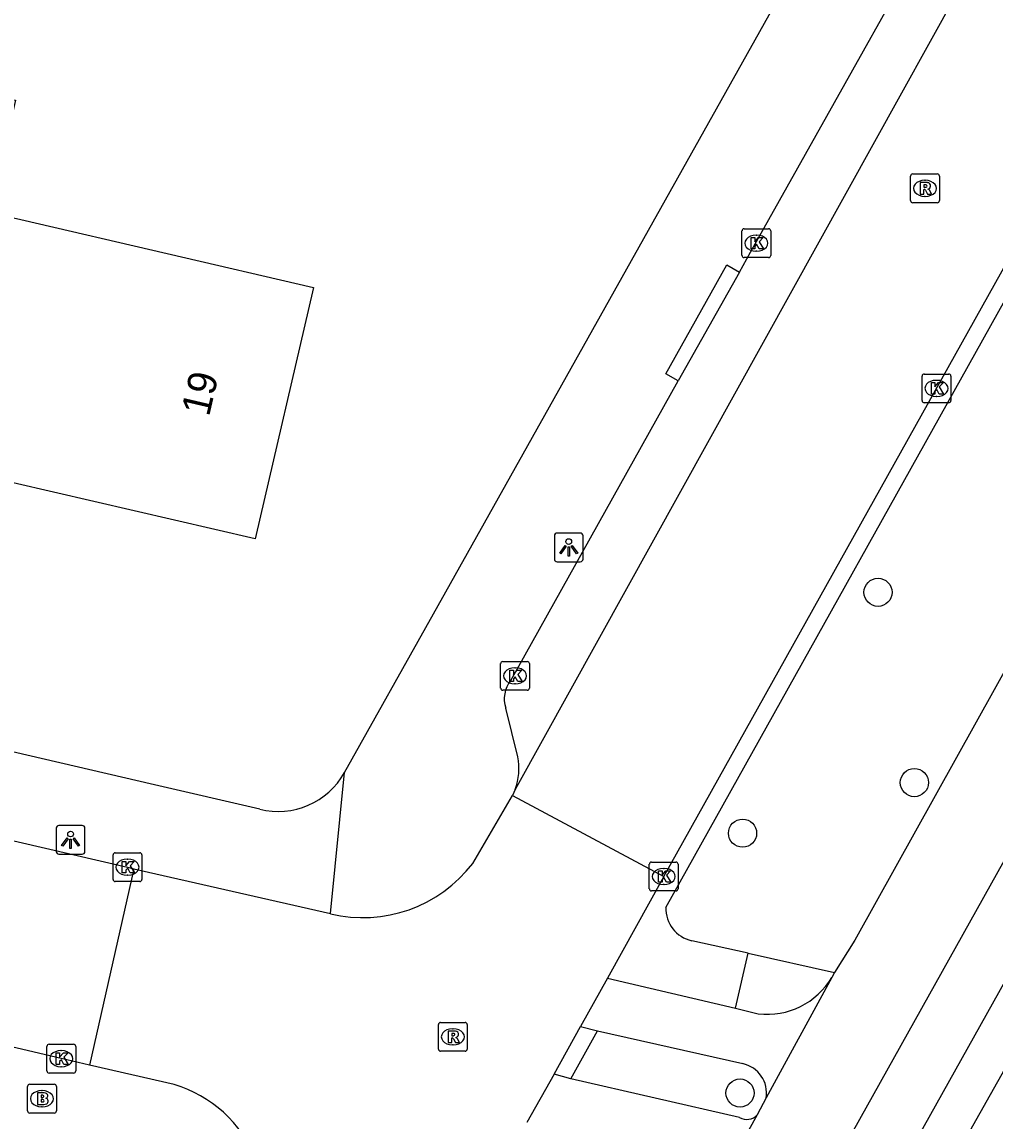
# Model space of a CAD drawing. Extents: x 162186 to 163152, y 385513 to 386513.
# Drawn here: x 162742.5 to 162776.34, y 385892.33 to 385930.55 of the extents above; entities that cross this region are included whole.
import ezdxf

# ---------------------------------------------------------------- set-up
doc = ezdxf.new("R2010")
doc.units = 0
for name, color, linetype in [('IMGEO_Boom', 7, 'Continuous'), ('IMGEO_Brandkraan', 7, 'Continuous'), ('IMGEO_Fietspad_gesloten', 7, 'Continuous'), ('IMGEO_Fietspad_open', 7, 'Continuous'), ('IMGEO_Groenvoorziening', 7, 'Continuous'), ('IMGEO_Kolk', 7, 'Continuous'), ('IMGEO_Lichtpunt', 7, 'Continuous'), ('IMGEO_Pand', 7, 'Continuous'), ('IMGEO_Pand_nummerreeks', 7, 'Continuous'), ('IMGEO_Rijbaan_lokaal_gesloten', 7, 'Continuous'), ('IMGEO_Rijbaan_lokaal_open', 7, 'Continuous'), ('IMGEO_Rioolput', 7, 'Continuous'), ('IMGEO_Voetpad_open', 7, 'Continuous')]:
    doc.layers.add(name, color=color, linetype=linetype)

msp = doc.modelspace()

# ---------------------------------------------------------------- linework, layer by layer
at = {"layer": 'IMGEO_Boom'}
for centre in [(162772.272, 385910.719), (162773.537, 385904.102), (162767.563, 385902.343), (162767.474, 385893.308)]:
    msp.add_circle(centre, 0.489, dxfattribs=at)
at = {"layer": 'IMGEO_Brandkraan'}
for p, q in [((162742.699, 385892.685), (162742.699, 385893.537)), ((162742.774, 385893.611), (162743.626, 385893.611)), ((162743.7, 385893.537), (162743.7, 385892.685)), ((162743.187, 385893.391), (162743.212, 385893.391)), ((162743.21, 385892.831), (162743.185, 385892.831)), ((162743.626, 385892.611), (162742.774, 385892.611))]:
    msp.add_line(p, q, dxfattribs=at)
for points in [[(162742.699, 385892.685), (162742.699, 385893.537)], [(162742.774, 385893.611), (162743.626, 385893.611)], [(162743.7, 385893.537), (162743.7, 385892.685)], [(162743.047, 385893.311), (162743.047, 385892.911), (162743.26, 385892.911)], [(162743.278, 385893.311), (162743.047, 385893.311)], [(162743.226, 385893.23), (162743.172, 385893.23), (162743.172, 385893.154)], [(162743.172, 385893.154), (162743.225, 385893.154)], [(162743.234, 385893.078), (162743.172, 385893.078), (162743.172, 385892.997)], [(162743.172, 385892.997), (162743.234, 385892.997)], [(162743.626, 385892.611), (162742.774, 385892.611)]]:
    msp.add_lwpolyline(points, dxfattribs=at)
for centre, radius, start, end in [((162742.776, 385893.535), 0.0765, 91.552, 178.448), ((162742.776, 385893.535), 0.0765, 91.552, 178.448), ((162743.624, 385893.535), 0.0765, 1.552, 88.448), ((162743.624, 385893.535), 0.0765, 1.552, 88.448), ((162743.227, 385893.192), 0.0379, 267.8285, 90.9355), ((162743.235, 385893.037), 0.0404, 269.8759, 90.5077), ((162743.282, 385893.166), 0.145, 59.4692, 91.5367), ((162743.307, 385893.213), 0.0922, 285.5137, 58.1501), ((162743.312, 385893.021), 0.105, 301.3115, 78.989), ((162742.776, 385892.687), 0.0765, 181.552, 268.448), ((162742.776, 385892.687), 0.0765, 181.552, 268.448), ((162743.266, 385893.162), 0.251, 268.6676, 293.5347), ((162743.624, 385892.687), 0.0765, 271.552, 358.448), ((162743.624, 385892.687), 0.0765, 271.552, 358.448)]:
    msp.add_arc(centre, radius, start, end, dxfattribs=at)
for centre, major_axis, ratio, start_param, end_param in [((162743.186, 385893.111), (-0.387, 0.002), 0.722429, 4.712389, 7.853982), ((162743.211, 385893.111), (-0.39, 0.002), 0.717154, 1.570796, 4.712389)]:
    msp.add_ellipse(centre, major_axis=major_axis, ratio=ratio, start_param=start_param, end_param=end_param, dxfattribs=at)
at = {"layer": 'IMGEO_Fietspad_gesloten'}
for points in [[(162733.132, 385823.472), (162733.264, 385823.709), (162792.26, 385929.313)], [(162788.232, 385928.737), (162771.467, 385898.628), (162770.754, 385897.494)], [(162770.665, 385897.33), (162768.38, 385893.136)], [(162770.754, 385897.494), (162770.665, 385897.33)], [(162768.38, 385893.136), (162768.075, 385892.55)], [(162768.075, 385892.55), (162765.221, 385887.388)]]:
    msp.add_lwpolyline(points, dxfattribs=at)
at = {"layer": 'IMGEO_Fietspad_open'}
for points in [[(162762.86, 385897.299), (162767.318, 385896.262)], [(162767.318, 385896.262), (162768.11, 385896.062)], [(162761.927, 385895.622), (162762.521, 385895.466)], [(162762.521, 385895.466), (162767.566, 385894.331)], [(162761.592, 385893.803), (162761.006, 385893.96)], [(162767.459, 385892.452), (162761.592, 385893.803)]]:
    msp.add_lwpolyline(points, dxfattribs=at)
for centre, radius, start, end in [((162768.41, 385898.666), 2.621, 263.4315, 329.3572), ((162767.353, 385893.311), 1.041, 350.3026, 78.2206), ((162767.704, 385892.9), 0.51, 241.3748, 316.7042)]:
    msp.add_arc(centre, radius, start, end, dxfattribs=at)
at = {"layer": 'IMGEO_Groenvoorziening'}
msp.add_lwpolyline([(162785.089, 385909.052), (162751.168, 385848.896), (162746.358, 385840.366)], dxfattribs=at)
at = {"layer": 'IMGEO_Kolk'}
for p, q in [((162767.542, 385922.433), (162767.542, 385923.285)), ((162767.617, 385923.359), (162768.469, 385923.359)), ((162768.543, 385923.285), (162768.543, 385922.433)), ((162768.03, 385923.139), (162768.055, 385923.139)), ((162768.053, 385922.579), (162768.028, 385922.579)), ((162768.469, 385922.359), (162767.617, 385922.359)), ((162773.881, 385918.31), (162774.733, 385918.31)), ((162773.806, 385917.384), (162773.806, 385918.236)), ((162774.294, 385918.09), (162774.319, 385918.09)), ((162774.807, 385918.236), (162774.807, 385917.384)), ((162774.317, 385917.53), (162774.292, 385917.53)), ((162774.733, 385917.31), (162773.881, 385917.31)), ((162759.15, 385907.387), (162759.15, 385908.239)), ((162759.225, 385908.313), (162760.077, 385908.313)), ((162759.638, 385908.093), (162759.663, 385908.093)), ((162760.151, 385908.239), (162760.151, 385907.387)), ((162760.077, 385907.313), (162759.225, 385907.313)), ((162759.661, 385907.533), (162759.636, 385907.533)), ((162745.672, 385900.735), (162745.672, 385901.587)), ((162745.747, 385901.661), (162746.599, 385901.661)), ((162746.673, 385901.587), (162746.673, 385900.735)), ((162746.16, 385901.441), (162746.185, 385901.441)), ((162764.32, 385900.41), (162764.32, 385901.262)), ((162764.395, 385901.336), (162765.247, 385901.336)), ((162764.808, 385901.116), (162764.833, 385901.116)), ((162765.321, 385901.262), (162765.321, 385900.41)), ((162746.183, 385900.881), (162746.158, 385900.881)), ((162746.599, 385900.661), (162745.747, 385900.661)), ((162765.247, 385900.336), (162764.395, 385900.336)), ((162764.831, 385900.556), (162764.806, 385900.556)), ((162743.446, 385895.003), (162744.298, 385895.003)), ((162743.371, 385894.077), (162743.371, 385894.929)), ((162743.859, 385894.783), (162743.884, 385894.783)), ((162744.372, 385894.929), (162744.372, 385894.077)), ((162743.882, 385894.223), (162743.857, 385894.223)), ((162744.298, 385894.003), (162743.446, 385894.003))]:
    msp.add_line(p, q, dxfattribs=at)
for points in [[(162767.542, 385922.433), (162767.542, 385923.285)], [(162767.617, 385923.359), (162768.469, 385923.359)], [(162768.543, 385923.285), (162768.543, 385922.433)], [(162767.863, 385923.059), (162767.986, 385923.059), (162767.986, 385922.908), (162768.116, 385923.059), (162768.28, 385923.059), (162768.134, 385922.908), (162768.287, 385922.659), (162768.135, 385922.659), (162768.05, 385922.823), (162767.986, 385922.756), (162767.986, 385922.659), (162767.863, 385922.659), (162767.863, 385923.059)], [(162768.469, 385922.359), (162767.617, 385922.359)], [(162773.881, 385918.31), (162774.733, 385918.31)], [(162773.806, 385917.384), (162773.806, 385918.236)], [(162774.127, 385918.01), (162774.25, 385918.01), (162774.25, 385917.859), (162774.38, 385918.01), (162774.544, 385918.01), (162774.398, 385917.859), (162774.551, 385917.61), (162774.399, 385917.61), (162774.314, 385917.774), (162774.25, 385917.707), (162774.25, 385917.61), (162774.127, 385917.61), (162774.127, 385918.01)], [(162774.807, 385918.236), (162774.807, 385917.384)], [(162774.733, 385917.31), (162773.881, 385917.31)], [(162759.15, 385907.387), (162759.15, 385908.239)], [(162759.225, 385908.313), (162760.077, 385908.313)], [(162759.471, 385908.013), (162759.594, 385908.013), (162759.594, 385907.862), (162759.724, 385908.013), (162759.888, 385908.013), (162759.742, 385907.862), (162759.895, 385907.613), (162759.743, 385907.613), (162759.658, 385907.777), (162759.594, 385907.71), (162759.594, 385907.613), (162759.471, 385907.613), (162759.471, 385908.013)], [(162760.151, 385908.239), (162760.151, 385907.387)], [(162760.077, 385907.313), (162759.225, 385907.313)], [(162745.672, 385900.735), (162745.672, 385901.587)], [(162745.747, 385901.661), (162746.599, 385901.661)], [(162746.673, 385901.587), (162746.673, 385900.735)], [(162745.993, 385901.361), (162746.116, 385901.361), (162746.116, 385901.21), (162746.246, 385901.361), (162746.41, 385901.361), (162746.264, 385901.21), (162746.417, 385900.961), (162746.265, 385900.961), (162746.18, 385901.125), (162746.116, 385901.058), (162746.116, 385900.961), (162745.993, 385900.961), (162745.993, 385901.361)], [(162764.32, 385900.41), (162764.32, 385901.262)], [(162764.395, 385901.336), (162765.247, 385901.336)], [(162765.321, 385901.262), (162765.321, 385900.41)], [(162764.641, 385901.036), (162764.764, 385901.036), (162764.764, 385900.885), (162764.894, 385901.036), (162765.058, 385901.036), (162764.912, 385900.885), (162765.065, 385900.636), (162764.913, 385900.636), (162764.828, 385900.8), (162764.764, 385900.733), (162764.764, 385900.636), (162764.641, 385900.636), (162764.641, 385901.036)], [(162746.599, 385900.661), (162745.747, 385900.661)], [(162765.247, 385900.336), (162764.395, 385900.336)], [(162743.446, 385895.003), (162744.298, 385895.003)], [(162743.371, 385894.077), (162743.371, 385894.929)], [(162743.692, 385894.703), (162743.815, 385894.703), (162743.815, 385894.552), (162743.945, 385894.703), (162744.109, 385894.703), (162743.963, 385894.552), (162744.116, 385894.303), (162743.964, 385894.303), (162743.879, 385894.467), (162743.815, 385894.4), (162743.815, 385894.303), (162743.692, 385894.303), (162743.692, 385894.703)], [(162744.372, 385894.929), (162744.372, 385894.077)], [(162744.298, 385894.003), (162743.446, 385894.003)]]:
    msp.add_lwpolyline(points, dxfattribs=at)
for centre, start, end in [((162767.619, 385923.283), 91.552, 178.448), ((162767.619, 385923.283), 91.552, 178.448), ((162768.467, 385923.283), 1.552, 88.448), ((162768.467, 385923.283), 1.552, 88.448), ((162767.619, 385922.435), 181.552, 268.448), ((162767.619, 385922.435), 181.552, 268.448), ((162768.467, 385922.435), 271.552, 358.448), ((162768.467, 385922.435), 271.552, 358.448), ((162773.883, 385918.234), 91.552, 178.448), ((162773.883, 385918.234), 91.552, 178.448), ((162774.731, 385918.234), 1.552, 88.448), ((162774.731, 385918.234), 1.552, 88.448), ((162773.883, 385917.386), 181.552, 268.448), ((162773.883, 385917.386), 181.552, 268.448), ((162774.731, 385917.386), 271.552, 358.448), ((162774.731, 385917.386), 271.552, 358.448), ((162759.227, 385908.237), 91.552, 178.448), ((162759.227, 385908.237), 91.552, 178.448), ((162760.075, 385908.237), 1.552, 88.448), ((162760.075, 385908.237), 1.552, 88.448), ((162759.227, 385907.389), 181.552, 268.448), ((162759.227, 385907.389), 181.552, 268.448), ((162760.075, 385907.389), 271.552, 358.448), ((162760.075, 385907.389), 271.552, 358.448), ((162745.749, 385901.585), 91.552, 178.448), ((162745.749, 385901.585), 91.552, 178.448), ((162746.597, 385901.585), 1.552, 88.448), ((162746.597, 385901.585), 1.552, 88.448), ((162764.397, 385901.26), 91.552, 178.448), ((162764.397, 385901.26), 91.552, 178.448), ((162765.245, 385901.26), 1.552, 88.448), ((162765.245, 385901.26), 1.552, 88.448), ((162745.749, 385900.737), 181.552, 268.448), ((162745.749, 385900.737), 181.552, 268.448), ((162746.597, 385900.737), 271.552, 358.448), ((162746.597, 385900.737), 271.552, 358.448), ((162764.397, 385900.412), 181.552, 268.448), ((162764.397, 385900.412), 181.552, 268.448), ((162765.245, 385900.412), 271.552, 358.448), ((162765.245, 385900.412), 271.552, 358.448), ((162743.448, 385894.927), 91.552, 178.448), ((162743.448, 385894.927), 91.552, 178.448), ((162744.296, 385894.927), 1.552, 88.448), ((162744.296, 385894.927), 1.552, 88.448), ((162743.448, 385894.079), 181.552, 268.448), ((162743.448, 385894.079), 181.552, 268.448), ((162744.296, 385894.079), 271.552, 358.448), ((162744.296, 385894.079), 271.552, 358.448)]:
    msp.add_arc(centre, 0.0765, start, end, dxfattribs=at)
for centre, major_axis, ratio, start_param, end_param in [((162768.029, 385922.859), (-0.387, 0.002), 0.722429, 4.712389, 7.853982), ((162768.054, 385922.859), (-0.39, 0.002), 0.717154, 1.570796, 4.712389), ((162774.293, 385917.81), (-0.387, 0.002), 0.722429, 4.712389, 7.853982), ((162774.318, 385917.81), (-0.39, 0.002), 0.717154, 1.570796, 4.712389), ((162759.637, 385907.813), (-0.387, 0.002), 0.722429, 4.712389, 7.853982), ((162759.662, 385907.813), (-0.39, 0.002), 0.717154, 1.570796, 4.712389), ((162746.159, 385901.161), (-0.387, 0.002), 0.722429, 4.712389, 7.853982), ((162746.184, 385901.161), (-0.39, 0.002), 0.717154, 1.570796, 4.712389), ((162764.807, 385900.836), (-0.387, 0.002), 0.722429, 4.712389, 7.853982), ((162764.832, 385900.836), (-0.39, 0.002), 0.717154, 1.570796, 4.712389), ((162743.858, 385894.503), (-0.387, 0.002), 0.722429, 4.712389, 7.853982), ((162743.883, 385894.503), (-0.39, 0.002), 0.717154, 1.570796, 4.712389)]:
    msp.add_ellipse(centre, major_axis=major_axis, ratio=ratio, start_param=start_param, end_param=end_param, dxfattribs=at)
at = {"layer": 'IMGEO_Lichtpunt'}
for p, q in [((162761.018, 385912.684), (162761.018, 385911.877)), ((162761.018, 385912.684), (162761.018, 385911.877)), ((162761.92, 385912.779), (162761.112, 385912.779)), ((162761.92, 385912.779), (162761.112, 385912.779)), ((162762.014, 385911.877), (162762.014, 385912.684)), ((162762.014, 385911.877), (162762.014, 385912.684)), ((162761.112, 385911.783), (162761.92, 385911.783)), ((162761.112, 385911.783), (162761.92, 385911.783)), ((162744.599, 385902.611), (162743.791, 385902.611)), ((162744.599, 385902.611), (162743.791, 385902.611)), ((162743.697, 385902.516), (162743.697, 385901.709)), ((162743.697, 385902.516), (162743.697, 385901.709)), ((162744.693, 385901.709), (162744.693, 385902.516)), ((162744.693, 385901.709), (162744.693, 385902.516)), ((162743.791, 385901.615), (162744.599, 385901.615)), ((162743.791, 385901.615), (162744.599, 385901.615))]:
    msp.add_line(p, q, dxfattribs=at)
for points in [[(162761.392, 385912.348), (162761.431, 385912.32), (162761.243, 385912.058), (162761.205, 385912.085), (162761.392, 385912.348)], [(162761.494, 385912.3), (162761.541, 385912.3), (162761.541, 385911.978), (162761.494, 385911.978), (162761.494, 385912.3)], [(162761.604, 385912.32), (162761.642, 385912.347), (162761.829, 385912.085), (162761.79, 385912.057), (162761.604, 385912.32)], [(162744.071, 385902.18), (162744.11, 385902.152), (162743.922, 385901.89), (162743.884, 385901.917), (162744.071, 385902.18)], [(162744.173, 385902.132), (162744.22, 385902.132), (162744.22, 385901.81), (162744.173, 385901.81), (162744.173, 385902.132)], [(162744.283, 385902.152), (162744.321, 385902.179), (162744.508, 385901.917), (162744.469, 385901.889), (162744.283, 385902.152)]]:
    msp.add_lwpolyline(points, dxfattribs=at)
for centre in [(162761.517, 385912.482), (162744.196, 385902.314)]:
    msp.add_circle(centre, 0.0994, dxfattribs=at)
for centre, start, end in [((162761.112, 385912.684), 90, 180), ((162761.112, 385912.684), 90, 180), ((162761.92, 385912.684), 0, 90), ((162761.92, 385912.684), 0, 90), ((162761.112, 385911.877), 180, 270), ((162761.112, 385911.877), 180, 270), ((162761.92, 385911.877), 270, 0), ((162761.92, 385911.877), 270, 360), ((162743.791, 385902.516), 90, 180), ((162743.791, 385902.516), 90, 180), ((162744.599, 385902.516), 0, 90), ((162744.599, 385902.516), 0, 90), ((162743.791, 385901.709), 180, 270), ((162743.791, 385901.709), 180, 270), ((162744.599, 385901.709), 270, 0), ((162744.599, 385901.709), 270, 360)]:
    msp.add_arc(centre, 0.0946, start, end, dxfattribs=at)
at = {"layer": 'IMGEO_Pand'}
msp.add_lwpolyline([(162735.446, 385929.41), (162741.942, 385927.905), (162742.278, 385927.827), (162741.375, 385923.931), (162742.469, 385923.678), (162752.641, 385921.321), (162750.615, 385912.579), (162740.788, 385914.856), (162742.035, 385920.237), (162733.921, 385922.827), (162735.446, 385929.41)], dxfattribs=at)
at = {"layer": 'IMGEO_Rijbaan_lokaal_gesloten'}
for points in [[(162790.338, 385959.176), (162759.651, 385903.858)], [(162764.82, 385900.836), (162774.27, 385917.746), (162791.04, 385947.784)], [(162759.651, 385903.858), (162759.564, 385903.659)]]:
    msp.add_lwpolyline(points, dxfattribs=at)
at = {"layer": 'IMGEO_Rijbaan_lokaal_open'}
for points in [[(162714.497, 385908.493), (162746.173, 385901.16), (162746.398, 385901.109)], [(162758.177, 385901.293), (162759.564, 385903.659)], [(162759.564, 385903.659), (162764.82, 385900.836)], [(162744.853, 385894.278), (162743.872, 385894.504), (162713.499, 385901.637)], [(162746.398, 385901.109), (162744.853, 385894.278)], [(162746.398, 385901.109), (162753.237, 385899.545)], [(162764.82, 385900.836), (162762.86, 385897.299)], [(162762.86, 385897.299), (162761.927, 385895.622)], [(162761.006, 385893.96), (162761.927, 385895.622)], [(162747.796, 385893.6), (162744.853, 385894.278)], [(162761.006, 385893.96), (162760.061, 385892.28)]]:
    msp.add_lwpolyline(points, dxfattribs=at)
for centre, radius, start, end in [((162754.37, 385904.196), 4.788, 256.3063, 322.6659), ((162746.56, 385889.387), 4.391, 330.107, 73.6439)]:
    msp.add_arc(centre, radius, start, end, dxfattribs=at)
at = {"layer": 'IMGEO_Rioolput'}
for p, q in [((162773.406, 385924.34), (162773.406, 385925.192)), ((162773.481, 385925.266), (162774.333, 385925.266)), ((162774.407, 385925.192), (162774.407, 385924.34)), ((162773.894, 385925.046), (162773.919, 385925.046)), ((162773.917, 385924.486), (162773.892, 385924.486)), ((162774.333, 385924.266), (162773.481, 385924.266)), ((162757.062, 385895.762), (162757.914, 385895.762)), ((162756.987, 385894.836), (162756.987, 385895.688)), ((162757.475, 385895.542), (162757.5, 385895.542)), ((162757.988, 385895.688), (162757.988, 385894.836)), ((162757.498, 385894.982), (162757.473, 385894.982)), ((162757.914, 385894.762), (162757.062, 385894.762))]:
    msp.add_line(p, q, dxfattribs=at)
for points in [[(162773.406, 385924.34), (162773.406, 385925.192)], [(162773.481, 385925.266), (162774.333, 385925.266)], [(162774.407, 385925.192), (162774.407, 385924.34)], [(162773.995, 385924.964), (162773.743, 385924.966), (162773.743, 385924.566)], [(162773.921, 385924.885), (162773.867, 385924.885), (162773.867, 385924.804)], [(162773.867, 385924.804), (162773.919, 385924.804)], [(162773.743, 385924.566), (162773.867, 385924.566), (162773.867, 385924.728), (162773.878, 385924.728)], [(162773.925, 385924.699), (162773.996, 385924.566), (162774.136, 385924.566), (162774.071, 385924.692)], [(162774.333, 385924.266), (162773.481, 385924.266)], [(162757.062, 385895.762), (162757.914, 385895.762)], [(162756.987, 385894.836), (162756.987, 385895.688)], [(162757.576, 385895.46), (162757.324, 385895.462), (162757.324, 385895.062)], [(162757.502, 385895.381), (162757.448, 385895.381), (162757.448, 385895.3)], [(162757.988, 385895.688), (162757.988, 385894.836)], [(162757.324, 385895.062), (162757.448, 385895.062), (162757.448, 385895.224), (162757.459, 385895.224)], [(162757.448, 385895.3), (162757.5, 385895.3)], [(162757.506, 385895.195), (162757.577, 385895.062), (162757.717, 385895.062), (162757.652, 385895.188)], [(162757.914, 385894.762), (162757.062, 385894.762)]]:
    msp.add_lwpolyline(points, dxfattribs=at)
for centre, radius, start, end in [((162773.483, 385925.19), 0.0765, 91.552, 178.448), ((162773.483, 385925.19), 0.0765, 91.552, 178.448), ((162774.331, 385925.19), 0.0765, 1.552, 88.448), ((162774.331, 385925.19), 0.0765, 1.552, 88.448), ((162773.903, 385924.993), 0.19, 274.7715, 282.9687), ((162773.927, 385924.789), 0.0964, 77.0061, 93.1865), ((162773.941, 385924.846), 0.0378, 276.6634, 79.6772), ((162773.994, 385924.854), 0.109, 350.3612, 89.416), ((162773.992, 385924.854), 0.112, 277.5842, 350.9817), ((162773.877, 385924.675), 0.0533, 26.0293, 88.6989), ((162773.976, 385924.639), 0.108, 29.5134, 73.7905), ((162773.483, 385924.342), 0.0765, 181.552, 268.448), ((162773.483, 385924.342), 0.0765, 181.552, 268.448), ((162774.331, 385924.342), 0.0765, 271.552, 358.448), ((162774.331, 385924.342), 0.0765, 271.552, 358.448), ((162757.064, 385895.686), 0.0765, 91.552, 178.448), ((162757.064, 385895.686), 0.0765, 91.552, 178.448), ((162757.912, 385895.686), 0.0765, 1.552, 88.448), ((162757.912, 385895.686), 0.0765, 1.552, 88.448), ((162757.508, 385895.285), 0.0964, 77.0061, 93.1865), ((162757.522, 385895.342), 0.0378, 276.6634, 79.6772), ((162757.575, 385895.35), 0.109, 350.3612, 89.416), ((162757.458, 385895.171), 0.0533, 26.0293, 88.6989), ((162757.484, 385895.489), 0.19, 274.7715, 282.9687), ((162757.573, 385895.35), 0.112, 277.5842, 350.9817), ((162757.557, 385895.135), 0.108, 29.5134, 73.7905), ((162757.064, 385894.838), 0.0765, 181.552, 268.448), ((162757.064, 385894.838), 0.0765, 181.552, 268.448), ((162757.912, 385894.838), 0.0765, 271.552, 358.448), ((162757.912, 385894.838), 0.0765, 271.552, 358.448)]:
    msp.add_arc(centre, radius, start, end, dxfattribs=at)
for centre, major_axis, ratio, start_param, end_param in [((162773.893, 385924.766), (-0.387, 0.002), 0.722429, 4.712389, 7.853982), ((162773.918, 385924.766), (-0.39, 0.002), 0.717154, 1.570796, 4.712389), ((162757.474, 385895.262), (-0.387, 0.002), 0.722429, 4.712389, 7.853982), ((162757.499, 385895.262), (-0.39, 0.002), 0.717154, 1.570796, 4.712389)]:
    msp.add_ellipse(centre, major_axis=major_axis, ratio=ratio, start_param=start_param, end_param=end_param, dxfattribs=at)
at = {"layer": 'IMGEO_Voetpad_open'}
for points in [[(162753.719, 385904.451), (162756.813, 385909.97), (162784.294, 385959.028)], [(162750.77, 385903.177), (162747.115, 385904.027), (162535.867, 385953.127)], [(162764.894, 385899.765), (162791.489, 385947.382), (162791.489, 385947.382)], [(162767.454, 385921.856), (162767.833, 385922.549), (162776.332, 385937.699)], [(162765.324, 385918.074), (162764.889, 385918.319), (162767.019, 385922.101), (162767.454, 385921.856)], [(162790.568, 385922.038), (162790.056, 385921.12), (162743.378, 385837.598)], [(162767.454, 385921.856), (162765.324, 385918.074)], [(162759.499, 385907.651), (162765.324, 385918.074)], [(162759.744, 385905.003), (162759.326, 385906.688)], [(162753.237, 385899.545), (162753.719, 385904.451)], [(162767.754, 385898.17), (162765.798, 385898.604)], [(162767.318, 385896.262), (162767.754, 385898.17)], [(162767.754, 385898.17), (162770.754, 385897.494)], [(162761.592, 385893.803), (162762.521, 385895.466)]]:
    msp.add_lwpolyline(points, dxfattribs=at)
for centre, radius, start, end in [((162760.297, 385907.011), 1.023, 141.2484, 198.3828), ((162757.727, 385904.591), 2.059, 339.1542, 11.5587), ((162751.405, 385905.757), 2.657, 256.1749, 330.5549), ((162766.039, 385899.724), 1.145, 177.9378, 257.8736)]:
    msp.add_arc(centre, radius, start, end, dxfattribs=at)

# ---------------------------------------------------------------- texts
at = {"layer": 'IMGEO_Pand_nummerreeks'}
msp.add_text('19', height=1, rotation=76.954, dxfattribs=at).set_placement((162749.007, 385916.803))

doc.saveas('drawing.dxf')
